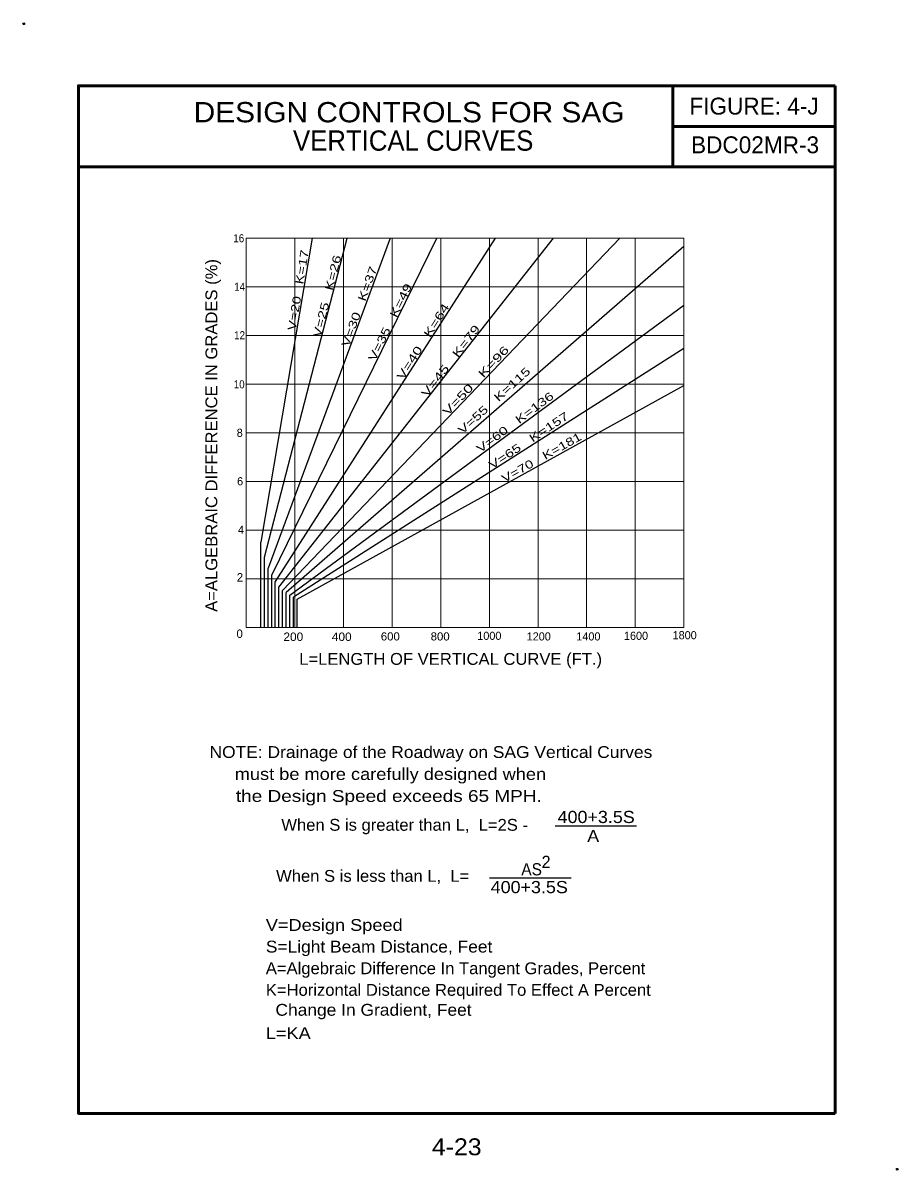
# Model space of a CAD drawing. Extents: x -165 to -84, y 65 to 172.
import ezdxf
from ezdxf.enums import TextEntityAlignment as Align

# ---------------------------------------------------------------- set-up
doc = ezdxf.new("R2010")
doc.units = 0
doc.header["$LTSCALE"] = 0.31
doc.header["$PDMODE"] = 32
doc.header["$PDSIZE"] = 0.155
doc.layers.add('1', color=7, linetype='Continuous', lineweight=25)
doc.layers.add('2', color=7, linetype='Continuous', lineweight=53)

msp = doc.modelspace()

# ---------------------------------------------------------------- linework, layer by layer
at = {"layer": '1', "lineweight": 13}
for p, q in [((-144.01, 151.624), (-103.51, 151.624)), ((-144.01, 151.624), (-144.01, 115.624)), ((-139.51, 151.624), (-139.51, 115.624)), ((-135.01, 151.624), (-135.01, 115.624)), ((-130.51, 151.624), (-130.51, 115.624)), ((-126.01, 151.624), (-126.01, 115.624)), ((-121.51, 151.624), (-121.51, 115.624)), ((-117.01, 151.624), (-117.01, 115.624)), ((-112.51, 151.624), (-112.51, 115.624)), ((-108.01, 151.624), (-108.01, 115.624)), ((-103.51, 151.624), (-103.51, 115.624)), ((-144.01, 147.124), (-103.51, 147.124)), ((-144.01, 142.624), (-103.51, 142.624)), ((-144.01, 138.124), (-103.51, 138.124)), ((-144.01, 133.624), (-103.51, 133.624)), ((-144.01, 129.124), (-103.51, 129.124)), ((-144.01, 124.624), (-103.51, 124.624)), ((-144.01, 120.124), (-103.51, 120.124)), ((-144.01, 115.624), (-103.51, 115.624)), ((-144.01, 115.624), (-103.51, 115.624))]:
    msp.add_line(p, q, dxfattribs=at)
at = {"layer": '1'}
for p, q in [((-137.89, 151.624), (-142.66, 123.499)), ((-142.322, 122.104), (-134.65, 151.624)), ((-130.69, 151.624), (-141.985, 121.091)), ((-141.647, 120.439), (-126.37, 151.624)), ((-120.97, 151.624), (-141.31, 119.854)), ((-140.972, 119.337), (-115.57, 151.624)), ((-109.45, 151.624), (-140.635, 119.021)), ((-103.51, 150.848), (-140.297, 118.841)), ((-139.96, 118.594), (-103.51, 145.406)), ((-103.51, 141.421), (-139.622, 118.414)), ((-139.285, 118.234), (-103.51, 138)), ((-142.66, 115.624), (-142.66, 123.499)), ((-142.322, 115.624), (-142.322, 122.104)), ((-141.985, 115.624), (-141.985, 121.091)), ((-141.647, 115.624), (-141.647, 120.439)), ((-141.31, 115.624), (-141.31, 119.854)), ((-140.972, 115.624), (-140.972, 119.337)), ((-140.635, 115.624), (-140.635, 119.021)), ((-140.297, 115.624), (-140.297, 118.841)), ((-139.96, 115.624), (-139.96, 118.594)), ((-139.622, 115.624), (-139.622, 118.414)), ((-139.285, 115.624), (-139.285, 118.234)), ((-115.428, 97.272), (-107.909, 97.272)), ((-121.5, 92.483), (-113.941, 92.483))]:
    msp.add_line(p, q, dxfattribs=at)
for p in [(-164.581, 171.43), (-83.781, 65.53)]:
    msp.add_point(p, dxfattribs=at)
at = {"layer": '2'}
for p, q in [((-104.529, 158.196), (-104.529, 165.696)), ((-89.529, 165.696), (-89.529, 70.696)), ((-104.529, 161.946), (-89.529, 161.946)), ((-104.529, 161.946), (-89.529, 161.946)), ((-89.529, 158.196), (-159.529, 158.196)), ((-89.529, 158.196), (-159.529, 158.196))]:
    msp.add_line(p, q, dxfattribs=at)
msp.add_lwpolyline([(-89.529, 70.696), (-159.529, 70.696), (-159.529, 165.696), (-89.529, 165.696)], dxfattribs=at)

# ---------------------------------------------------------------- texts
at = {"layer": '1'}
for s, height, p in [('BDC02MR-3', 1.563, (-96.9325, 159.459)), ('8', 0.75, (-144.6025, 133.24)), ('6', 0.75, (-144.568, 128.759)), ('4', 0.75, (-144.4905, 124.275)), ('2', 0.781, (-144.5805, 119.861)), ('0', 0.781, (-144.611, 114.649)), ('1000', 0.75, (-121.514, 114.471)), ('1200', 0.75, (-116.944, 114.415)), ('1400', 0.75, (-112.351, 114.415)), ('1600', 0.75, (-107.945, 114.471)), ('1800', 0.75, (-103.444, 114.527)), ('2', 1.125, (-116.264, 93.383))]:
    msp.add_text(s, height=height, dxfattribs=at).set_placement(p, align=Align.CENTER)
for s, height, width, p in [('16', 0.75, 0.9, (-144.692, 151.225)), ('14', 0.75, 0.9, (-144.6125, 146.742)), ('12', 0.75, 0.9, (-144.617, 142.259)), ('10', 0.75, 0.9, (-144.6505, 137.722)), ('200', 0.781, 1.05, (-139.646, 114.369)), ('400', 0.781, 1.05, (-135.166, 114.369)), ('600', 0.75, 1.05, (-130.675, 114.415)), ('800', 0.75, 1.05, (-126.062, 114.415)), ('L=LENGTH OF VERTICAL CURVE (FT.)', 1.093, 1.05, (-125.0935, 112.163)), ('400+3.5S', 1.125, 1.1, (-111.631, 97.536)), ('When S is greater than L,  L=2S -', 1.093, 1.05, (-129.3455, 96.823)), ('A', 1.125, 1.1, (-111.9055, 95.779)), ('AS', 1.125, 0.95, (-117.602, 92.698)), ('When S is less than L,  L=', 1.093, 1.05, (-132.3045, 92.101)), ('400+3.5S', 1.125, 1.1, (-117.82, 91.052))]:
    msp.add_text(s, height=height, dxfattribs=dict(at, width=width)).set_placement(p, align=Align.CENTER)
for s, height, rotation, width, p in [('A=ALGEBRAIC DIFFERENCE IN GRADES (%)', 1.093, 90, 1.05, (-146.678, 133.37)), ('V=20   K=17', 0.75, 80.645, 1.35, (-138.8261, 146.745)), ('V=25   K=26', 0.75, 75.625, 1.4, (-136.1678, 146.1474)), ('V=30   K=37', 0.75, 70.158, 1.4, (-133.1905, 145.1597)), ('V=35   K=49', 0.75, 63.86, 1.4, (-130.357, 143.6723)), ('V=40   K=64', 0.75, 57.611, 1.45, (-127.3313, 141.8471)), ('V=45   K=79', 0.75, 52.126, 1.45, (-124.7987, 140.0268)), ('V=50   K=96', 0.75, 46.767, 1.5, (-122.4947, 138.1801)), ('V=55   K=115', 0.75, 42.192, 1.4, (-120.8174, 136.315)), ('V=60   K=136', 0.75, 36.742, 1.4, (-118.9108, 134.2921)), ('V=65   K=157', 0.75, 33.566, 1.4, (-117.6733, 132.5946)), ('V=70   K=181', 0.75, 29.273, 1.35, (-116.5074, 130.9984))]:
    msp.add_text(s, height=height, rotation=rotation, dxfattribs=dict(at, width=width)).set_placement(p, align=Align.CENTER)
for s, height, width, p in [('NOTE: Drainage of the Roadway on SAG Vertical Curves', 1.094, 1.1, (-147.399, 103.552)), ('     must be more carefully designed when', 1.094, 1.15, (-147.399, 101.52)), ('     the Design Speed exceeds 65 MPH.', 1.094, 1.2, (-147.399, 99.489)), ('V=Design Speed', 1.093, 1.15, (-142.191, 87.563)), ('S=Light Beam Distance, Feet', 1.093, 1.1, (-142.191, 85.563)), ('A=Algebraic Difference In Tangent Grades, Percent', 1.093, 1.05, (-142.191, 83.563)), ('K=Horizontal Distance Required To Effect A Percent ', 1.093, 1.05, (-142.191, 81.563)), ('  Change In Gradient, Feet', 1.093, 1.1, (-142.191, 79.72)), ('L=KA', 1.093, 1.15, (-142.191, 77.563))]:
    msp.add_text(s, height=height, dxfattribs=dict(at, width=width)).set_placement(p)
at = {"layer": '2'}
msp.add_text('FIGURE: 4-J', height=1.563, dxfattribs=at).set_placement((-97.0285, 163.038), align=Align.CENTER)
for s, height, width, p in [('DESIGN CONTROLS FOR SAG ', 1.875, 1.1, (-128.5565, 162.32)), ('VERTICAL CURVES', 1.875, 0.95, (-128.5575, 159.695)), ('4-23', 1.563, 1.1, (-124.529, 66.82))]:
    msp.add_text(s, height=height, dxfattribs=dict(at, width=width)).set_placement(p, align=Align.CENTER)

doc.saveas('drawing.dxf')
